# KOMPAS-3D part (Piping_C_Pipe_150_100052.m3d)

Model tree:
1. Plane XY
2. Plane ZX
3. Plane ZY
4. X Axis
5. Y Axis
6. Z Axis
7. Origin
8. Path  (labels: Задвижка Dy 150; Труба Dy 150; Отвод 90 Dy 150)
9. Plane of section
10. Section of pipe
11. Pipe
     Толщина стенки 1 = 1

Referenced files in C:\Program Files\ASCON\KOMPAS-3D V10\Libs\Piping\Models\Tanks\: Tanks.a3d
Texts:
  Pipe Dn 150
  Steel ASTM A295
  Three Point Plane
  Plane at Angle
  Line and Point Plane
  Axis through Two Vertices
  Axis of Feature
  Axis of Conical Surface
  Axis through Edge
  Приклеить элемент выдавливания
  Приклеить элемент вращения
  Приклеить кинематический элемент
  Приклеить элемент по сечениям
  Trim by Surface
  Trim by Sketch
  Feature with No History
  Intersection Axis of Two Planes
  Two Line Plane
  Line and Face Plane
  Bend by line
  Hole in sheet body
  Cut in sheet body
  Point in CM
  Linear Dimension from Line to Point
  Surface Finish Symbol
  Geometric Tolerance Symbol
  Текст на чертеже
  Линия-выноска #1
  Линия-выноска #2
  Линия-выноска #3
  Отклонения формы и база
  Марка координационной оси
  Марка/позиционное обозначение с линией-выноской
  Марка/позиционное обозначение на линии
  Марка/позиционное обозначение без линии-выноски
  Задвижка Dy 150
  Труба Dy 150
  Отвод 90 Dy 150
